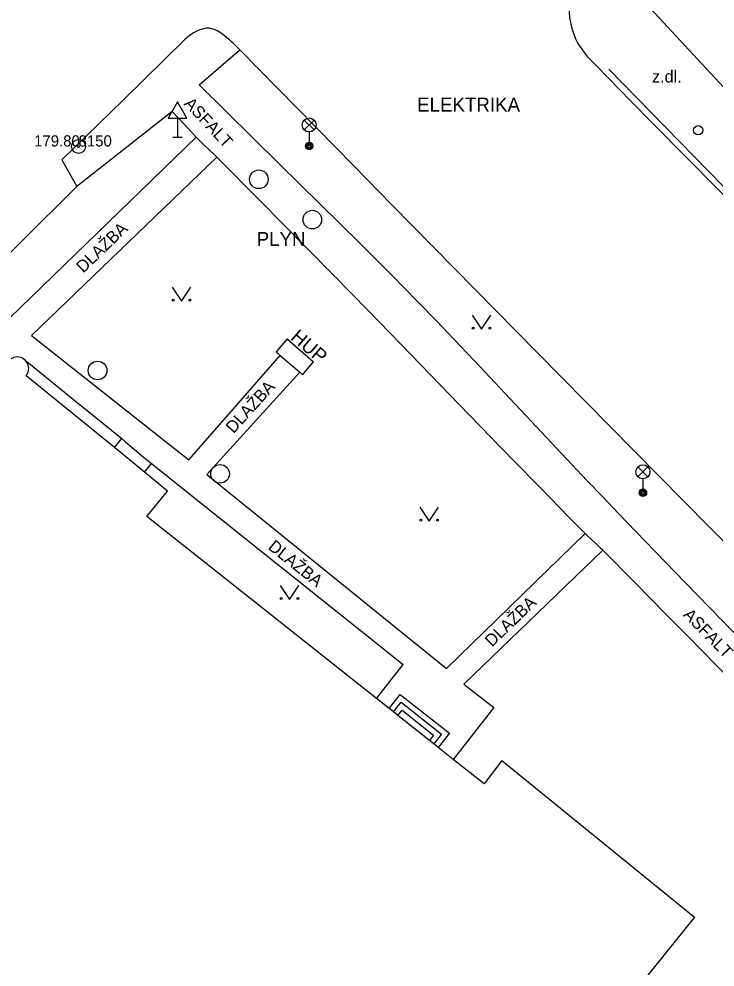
# Model space of a CAD drawing. Extents: x -538441 to -536770, y -1181008 to -1179809.
# Drawn here: x -537698.6 to -537661.2, y -1180844.3 to -1180793.5 of the extents above; entities that cross this region are included whole.
import ezdxf

# ---------------------------------------------------------------- set-up
doc = ezdxf.new("R2010")
doc.units = 0
for name, color, linetype in [('Vrstva 10', 7, 'Continuous'), ('Vrstva 11', 7, 'Continuous'), ('Vrstva 21', 7, 'Continuous'), ('Vrstva 22', 7, 'Continuous'), ('Vrstva 23', 7, 'Continuous'), ('Vrstva 24', 7, 'Continuous'), ('Vrstva 27', 7, 'Continuous'), ('Vrstva 28', 7, 'Continuous'), ('Vrstva 33', 7, 'Continuous'), ('Vrstva 34', 7, 'Continuous'), ('Vrstva 36', 7, 'Continuous'), ('Vrstva 40', 7, 'Continuous'), ('Vrstva 41', 7, 'Continuous'), ('Vrstva 42', 7, 'Continuous'), ('Vrstva 5', 7, 'Continuous'), ('Vrstva 9', 7, 'Continuous')]:
    doc.layers.add(name, color=color, linetype=linetype)

msp = doc.modelspace()

# ---------------------------------------------------------------- linework, layer by layer
at = {"layer": 'Vrstva 10'}
for p, q in [((-537668.61, -1180794.765), (-537668.117, -1180795.449)), ((-537692.98, -1180797.78), (-537696.28, -1180801.01)), ((-537670.782, -1180811.333), (-537678.58, -1180803.41)), ((-537662.981, -1180819.253), (-537670.782, -1180811.333)), ((-537657.778, -1180824.53), (-537662.981, -1180819.253))]:
    msp.add_line(p, q, dxfattribs=at)
for points in [[(-537667.726, -1180789.67), (-537668.125, -1180790.097), (-537668.463, -1180790.575), (-537668.732, -1180791.095), (-537668.928, -1180791.646), (-537669.047, -1180792.219), (-537669.087, -1180792.803), (-537669.047, -1180793.386), (-537668.927, -1180793.959), (-537668.731, -1180794.51), (-537668.61, -1180794.765)], [(-537683.68, -1180798.217), (-537686.74, -1180795.1), (-537686.937, -1180794.903), (-537687.087, -1180794.76), (-537687.202, -1180794.654), (-537687.29, -1180794.575), (-537687.427, -1180794.458), (-537687.57, -1180794.34), (-537687.625, -1180794.297), (-537687.732, -1180794.22), (-537687.83, -1180794.158), (-537687.917, -1180794.108), (-537687.995, -1180794.068), (-537688.064, -1180794.037), (-537688.124, -1180794.013), (-537688.177, -1180793.995), (-537688.224, -1180793.981), (-537688.304, -1180793.962), (-537688.364, -1180793.952), (-537688.409, -1180793.948), (-537688.475, -1180793.946), (-537688.54, -1180793.95), (-537688.613, -1180793.961), (-537688.683, -1180793.975), (-537688.749, -1180793.992), (-537688.812, -1180794.01), (-537688.87, -1180794.031), (-537688.98, -1180794.075), (-537689.076, -1180794.12), (-537689.158, -1180794.163), (-537689.23, -1180794.204), (-537689.291, -1180794.242), (-537689.396, -1180794.313), (-537689.471, -1180794.369), (-537689.526, -1180794.413), (-537689.605, -1180794.48), (-537689.68, -1180794.55), (-537692.98, -1180797.78)], [(-537668.117, -1180795.449), (-537667.647, -1180795.926), (-537666.978, -1180796.614), (-537665.721, -1180797.899)], [(-537665.721, -1180797.899), (-537664.62, -1180799.018), (-537662.692, -1180800.972), (-537659.801, -1180803.9), (-537658.359, -1180805.367), (-537657.639, -1180806.103)], [(-537678.58, -1180803.41), (-537680.621, -1180801.334), (-537683.68, -1180798.217)]]:
    msp.add_lwpolyline(points, dxfattribs=at)
at = {"layer": 'Vrstva 11'}
for p, q in [((-537688.92, -1180796.99), (-537686.74, -1180795.1)), ((-537684.615, -1180801.23), (-537688.92, -1180796.99)), ((-537690.37, -1180798.41), (-537695.49, -1180802.44)), ((-537689.08, -1180799.79), (-537699.091, -1180809.494)), ((-537687.98, -1180800.86), (-537697.914, -1180810.423)), ((-537696.28, -1180801.01), (-537695.49, -1180802.44)), ((-537680.31, -1180805.47), (-537684.615, -1180801.23)), ((-537697.914, -1180810.423), (-537689.48, -1180817.08)), ((-537674.448, -1180814.654), (-537678.067, -1180810.925)), ((-537689.48, -1180817.08), (-537684.57, -1180811.501)), ((-537668.104, -1180818.206), (-537674.153, -1180811.784)), ((-537688.51, -1180817.88), (-537683.529, -1180812.395)), ((-537693.465, -1180816.435), (-537693.07, -1180815.95)), ((-537691.853, -1180817.748), (-537691.48, -1180817.29)), ((-537691.48, -1180817.29), (-537684.725, -1180822.675)), ((-537688.51, -1180817.88), (-537675.65, -1180828.28)), ((-537675.65, -1180828.28), (-537668.22, -1180821.03)), ((-537667.27, -1180821.93), (-537674.72, -1180829.11)), ((-537684.725, -1180822.675), (-537677.97, -1180828.06)), ((-537679.4, -1180829.89), (-537677.97, -1180828.06)), ((-537674.72, -1180829.11), (-537673.11, -1180830.36)), ((-537673.11, -1180830.36), (-537675.29, -1180833.145))]:
    msp.add_line(p, q, dxfattribs=at)
for points in [[(-537683.267, -1180805.62), (-537685.621, -1180803.238), (-537687.98, -1180800.86), (-537688.116, -1180800.725), (-537688.359, -1180800.493), (-537688.725, -1180800.147), (-537688.905, -1180799.971), (-537689.08, -1180799.79), (-537689.725, -1180799.1), (-537690.37, -1180798.41)], [(-537695.49, -1180802.44), (-537698.505, -1180805.445), (-537701.52, -1180808.45), (-537702.05, -1180808.972), (-537702.551, -1180809.457)], [(-537674.153, -1180811.784), (-537674.912, -1180810.984), (-537675.578, -1180810.287), (-537676.162, -1180809.677), (-537677.189, -1180808.616), (-537677.963, -1180807.823), (-537678.546, -1180807.231), (-537679.425, -1180806.348), (-537679.867, -1180805.908), (-537680.31, -1180805.47)], [(-537678.067, -1180810.925), (-537679.881, -1180809.065), (-537680.79, -1180808.137), (-537681.7, -1180807.21), (-537683.267, -1180805.62)], [(-537698.253, -1180811.745), (-537695.662, -1180813.848), (-537693.07, -1180815.95), (-537692.869, -1180816.115), (-537692.523, -1180816.41), (-537692.005, -1180816.855), (-537691.744, -1180817.075), (-537691.48, -1180817.29)], [(-537670.651, -1180818.555), (-537672.033, -1180817.138), (-537674.448, -1180814.654)], [(-537666.428, -1180819.966), (-537667.294, -1180819.059), (-537668.104, -1180818.206)], [(-537662.705, -1180826.548), (-537663.844, -1180825.391), (-537665.555, -1180823.658), (-537667.27, -1180821.93), (-537667.387, -1180821.815), (-537667.595, -1180821.619), (-537667.911, -1180821.328), (-537668.067, -1180821.181), (-537668.22, -1180821.03), (-537669.067, -1180820.171), (-537670.651, -1180818.555)], [(-537658.414, -1180828.221), (-537660.189, -1180826.402), (-537662.847, -1180823.669), (-537665.5, -1180820.93), (-537666.428, -1180819.966)], [(-537656.482, -1180832.909), (-537659.17, -1180830.156), (-537661.189, -1180828.093), (-537662.705, -1180826.548)], [(-537678.731, -1180830.419), (-537678.13, -1180829.66), (-537675.501, -1180831.744), (-537676.102, -1180832.502)], [(-537678.496, -1180830.605), (-537678.081, -1180830.082), (-537675.922, -1180831.793), (-537676.337, -1180832.316)], [(-537678.261, -1180830.791), (-537678.032, -1180830.503), (-537676.344, -1180831.841), (-537676.572, -1180832.129)]]:
    msp.add_lwpolyline(points, dxfattribs=at)
at = {"layer": 'Vrstva 21'}
for radius in [0.375, 0.05]:
    msp.add_circle((-537695.39, -1180800.29), radius, dxfattribs=at)
at = {"layer": 'Vrstva 24'}
for p, q in [((-537684.2, -1180810.61), (-537684.798, -1180811.306)), ((-537684.2, -1180810.61), (-537682.78, -1180811.83)), ((-537683.378, -1180812.526), (-537682.78, -1180811.83))]:
    msp.add_line(p, q, dxfattribs=at)
msp.add_lwpolyline([(-537684.798, -1180811.306), (-537684.57, -1180811.501), (-537683.529, -1180812.395), (-537683.378, -1180812.526)], dxfattribs=at)
at = {"layer": 'Vrstva 27'}
for centre in [(-537685.72, -1180802.05), (-537682.85, -1180804.21), (-537694.37, -1180812.3), (-537687.8, -1180817.84)]:
    msp.add_circle(centre, 0.5, dxfattribs=at)
at = {"layer": 'Vrstva 28'}
msp.add_circle((-537662.152, -1180799.423), 0.25, dxfattribs=at)
at = {"layer": 'Vrstva 33'}
for p, q in [((-537683.285, -1180799.4), (-537682.755, -1180798.87)), ((-537683.285, -1180798.87), (-537682.755, -1180799.4)), ((-537683.02, -1180799.51), (-537683.02, -1180800.26)), ((-537665.383, -1180817.991), (-537664.853, -1180817.461)), ((-537665.383, -1180817.461), (-537664.853, -1180817.991)), ((-537665.118, -1180818.101), (-537665.118, -1180818.851))]:
    msp.add_line(p, q, dxfattribs=at)
for centre, radius in [((-537683.02, -1180799.135), 0.375), ((-537683.02, -1180800.26), 0.2), ((-537683.02, -1180800.26), 0.145), ((-537683.02, -1180800.26), 0.0876), ((-537665.118, -1180817.726), 0.375), ((-537665.118, -1180818.851), 0.2), ((-537665.118, -1180818.851), 0.145), ((-537665.118, -1180818.851), 0.0876)]:
    msp.add_circle(centre, radius, dxfattribs=at)
at = {"layer": 'Vrstva 34'}
for p, q in [((-537690.078, -1180798.764), (-537690.078, -1180799.782)), ((-537690.328, -1180799.782), (-537689.828, -1180799.782))]:
    msp.add_line(p, q, dxfattribs=at)
msp.add_lwpolyline([(-537690.578, -1180798.764), (-537689.578, -1180798.764), (-537690.078, -1180797.898)], close=True, dxfattribs=at)
at = {"layer": 'Vrstva 36'}
for points in [[(-537690.364, -1180807.829), (-537689.864, -1180808.579), (-537689.364, -1180807.829)], [(-537674.28, -1180809.328), (-537673.78, -1180810.078), (-537673.28, -1180809.328)], [(-537677.077, -1180819.625), (-537676.577, -1180820.375), (-537676.077, -1180819.625)], [(-537684.57, -1180823.824), (-537684.07, -1180824.574), (-537683.57, -1180823.824)]]:
    msp.add_lwpolyline(points, dxfattribs=at)
for centre in [(-537690.314, -1180808.529), (-537689.415, -1180808.529), (-537674.23, -1180810.028), (-537673.331, -1180810.028), (-537677.027, -1180820.325), (-537676.128, -1180820.325), (-537684.52, -1180824.524), (-537683.621, -1180824.524)]:
    msp.add_circle(centre, 0.05, dxfattribs=at)
at = {"layer": 'Vrstva 5'}
for p, q in [((-537691.724, -1180820.128), (-537690.61, -1180818.76)), ((-537672.68, -1180833.2), (-537673.63, -1180834.46)), ((-537672.68, -1180833.2), (-537670.108, -1180835.294)), ((-537670.108, -1180835.294), (-537662.35, -1180841.61))]:
    msp.add_line(p, q, dxfattribs=at)
for points in [[(-537666.11, -1180791.38), (-537659.868, -1180798.114), (-537658.782, -1180799.285), (-537657.99, -1180800.14)], [(-537698.253, -1180811.745), (-537698.438, -1180811.623), (-537698.654, -1180811.574), (-537698.874, -1180811.604), (-537699.069, -1180811.71), (-537699.214, -1180811.877), (-537699.291, -1180812.085), (-537699.29, -1180812.307), (-537699.28, -1180812.35)], [(-537698.2, -1180812.58), (-537698.094, -1180812.385), (-537698.064, -1180812.165), (-537698.112, -1180811.949), (-537698.253, -1180811.745)], [(-537690.61, -1180818.76), (-537691.853, -1180817.748), (-537693.465, -1180816.435), (-537698.2, -1180812.58)], [(-537673.63, -1180834.46), (-537675.29, -1180833.145), (-537676.102, -1180832.502), (-537676.337, -1180832.316), (-537676.572, -1180832.129), (-537678.261, -1180830.791), (-537678.496, -1180830.605), (-537678.731, -1180830.419), (-537679.4, -1180829.89), (-537691.724, -1180820.128)], [(-537662.35, -1180841.61), (-537672.852, -1180854.633), (-537674.037, -1180856.103), (-537674.997, -1180857.294), (-537675.216, -1180857.566), (-537676.563, -1180859.236), (-537676.783, -1180859.509), (-537678.474, -1180861.605), (-537679.759, -1180863.199), (-537682.05, -1180866.04)]]:
    msp.add_lwpolyline(points, dxfattribs=at)
at = {"layer": 'Vrstva 9'}
msp.add_line((-537645.937, -1180817.628), (-537666.95, -1180796.149), dxfattribs=at)

# ---------------------------------------------------------------- texts
at = {"layer": 'Vrstva 22'}
msp.add_text('179.80 ', height=0.6, dxfattribs=at).set_placement((-537697.775, -1180800.29))
at = {"layer": 'Vrstva 23'}
msp.add_text('8150', height=0.6, dxfattribs=at).set_placement((-537695.39, -1180800.29))
at = {"layer": 'Vrstva 40'}
msp.add_text('z.dl.', height=0.65, dxfattribs=at).set_placement((-537664.629, -1180796.86))
for s, rotation, p in [('ASFALT', 313.0694, (-537689.772, -1180798.025)), ('DLAŽBA', 43.9099, (-537695.136, -1180807.104)), ('DLAŽBA', 47.757, (-537687.079, -1180815.712)), ('DLAŽBA', 321.4386, (-537685.267, -1180821.837)), ('DLAŽBA', 43.9427, (-537673.215, -1180827.151)), ('ASFALT', 314.4812, (-537662.999, -1180825.434))]:
    msp.add_text(s, height=0.65, rotation=rotation, dxfattribs=at).set_placement(p)
at = {"layer": 'Vrstva 41'}
msp.add_text('HUP', height=0.75, rotation=319.3323, dxfattribs=at).set_placement((-537684.063, -1180810.596))
at = {"layer": 'Vrstva 42'}
for s, p in [('ELEKTRIKA', (-537677.228, -1180798.419)), ('PLYN', (-537685.835, -1180805.625))]:
    msp.add_text(s, height=0.75, dxfattribs=at).set_placement(p)

doc.saveas('drawing.dxf')
